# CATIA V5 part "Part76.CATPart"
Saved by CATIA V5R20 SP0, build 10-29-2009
Part number: FA 053000-1
Revision: ANY
Definition: UNKNOWN
Nomenclature: FA 053000-1
Source: Unknown
Bounding box of the stored display mesh (mm): x -1.9 to 1.9, y -1.1 to 2.45, z -1.9 to 1.9
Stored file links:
  C:\Users\Utente\Desktop\IO LAVORO\3D X SITO CF\CUMSA\3D files FA\FA 053004-21\Part76.CATPart

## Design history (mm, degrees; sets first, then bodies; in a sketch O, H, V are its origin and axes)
Body1 "Cortar-Extruir1" (main body)
  Solid1: solid without history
